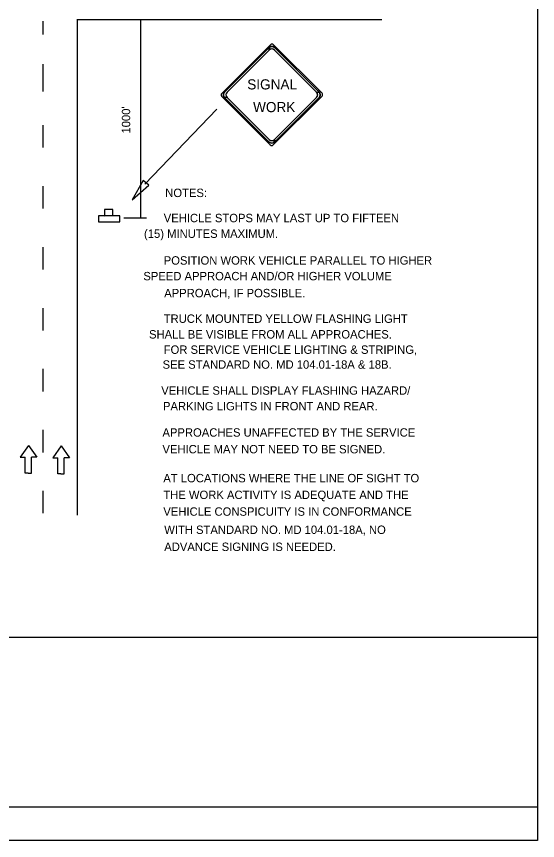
# Model space of a CAD drawing. Extents: x 1531.2 to 1538.6, y 1529.6 to 1539.9.
# Drawn here: x 1534.86 to 1538.58, y 1529.59 to 1535.48 of the extents above; entities that cross this region are included whole.
import ezdxf

# ---------------------------------------------------------------- set-up
doc = ezdxf.new("R2010")
doc.units = 0
for name, color, linetype in [('BORD-LINE', 7, 'Continuous'), ('DETL-DIMS', 7, 'Continuous'), ('DETL-LINE', 7, 'Continuous'), ('DETL-NOTE', 7, 'Continuous'), ('TTLB-TEXT', 7, 'Continuous'), ('USER-BORD', 7, 'Continuous')]:
    doc.layers.add(name, color=color, linetype=linetype)

# ---------------------------------------------------------------- blocks, each defined once
blk = doc.blocks.new('SIGN13')
at = {"layer": 'USER-BORD'}
for points in [[(-0.0134, 0.0182), (0.011, 0.0189), (0.011, 0.0371), (-0.0134, 0.0371)], [(-0.0314, 0.0182), (-0.0314, 0), (0.032, 0), (0.032, 0.0182)]]:
    blk.add_lwpolyline(points, close=True, dxfattribs=at)
blk = doc.blocks.new('DIR2')
at = {"layer": 'USER-BORD'}
for p, q in [((0, 0.0012), (-0.0342, -0.0477)), ((0, 0.0012), (0.0342, -0.0477)), ((-0.0342, -0.0477), (-0.0132, -0.0477)), ((-0.0132, -0.1133), (-0.0132, -0.0477)), ((0.0342, -0.0477), (0.0132, -0.0477)), ((0.0132, -0.1133), (0.0132, -0.0477)), ((-0.0011, -0.1133), (-0.0132, -0.1133)), ((-0.0011, -0.1133), (0.0011, -0.1133)), ((0.0011, -0.1133), (0.0132, -0.1133))]:
    blk.add_line(p, q, dxfattribs=at)

msp = doc.modelspace()

# ---------------------------------------------------------------- linework, layer by layer
at = {"layer": 'BORD-LINE'}
for p, q in [((1538.5844, 1539.9414), (1538.5844, 1531.0427)), ((1538.5844, 1531.0427), (1531.2124, 1531.0427)), ((1538.5844, 1531.0427), (1538.5844, 1529.5924)), ((1534.1128, 1529.8341), (1538.5844, 1529.8341)), ((1538.5844, 1529.5924), (1531.2124, 1529.5924))]:
    msp.add_line(p, q, dxfattribs=at)
at = {"layer": 'DETL-DIMS'}
for p, q in [((1535.7503, 1534.043), (1535.7503, 1535.4613)), ((1535.78, 1534.2836), (1536.2948, 1534.8185)), ((1535.6308, 1534.043), (1535.7909, 1534.043))]:
    msp.add_line(p, q, dxfattribs=at)
msp.add_lwpolyline([(1535.8076, 1534.2773), (1535.767, 1534.3102), (1535.6884, 1534.172)], close=True, dxfattribs=at)
at = {"layer": 'DETL-LINE'}
for p, q in [((1535.2981, 1535.092), (1535.2981, 1535.4633)), ((1535.2981, 1535.4613), (1537.4718, 1535.4613)), ((1535.054, 1535.3527), (1535.054, 1535.4485)), ((1536.6766, 1535.2801), (1536.3287, 1534.9322)), ((1536.3483, 1534.9404), (1536.6682, 1535.2603)), ((1536.6682, 1535.2419), (1536.3667, 1534.9404)), ((1537.0453, 1534.933), (1536.6982, 1535.2801)), ((1537.0065, 1534.9404), (1536.705, 1535.2419)), ((1536.7051, 1535.2603), (1537.025, 1534.9404)), ((1535.054, 1534.9801), (1535.054, 1535.1401)), ((1535.054, 1534.9463), (1535.054, 1535.1063)), ((1535.2981, 1531.9169), (1535.2981, 1535.092)), ((1536.3287, 1534.9107), (1536.6758, 1534.5636)), ((1536.6682, 1534.5836), (1536.3483, 1534.9035)), ((1536.3667, 1534.9035), (1536.6682, 1534.602)), ((1536.6974, 1534.5636), (1537.0453, 1534.9115)), ((1537.025, 1534.9035), (1536.7051, 1534.5836)), ((1536.7051, 1534.602), (1537.0065, 1534.9035)), ((1535.054, 1534.5445), (1535.054, 1534.7045)), ((1535.054, 1534.1089), (1535.054, 1534.269)), ((1535.054, 1533.6734), (1535.054, 1533.8334)), ((1535.054, 1533.2378), (1535.054, 1533.3979)), ((1535.054, 1532.8023), (1535.054, 1532.9623)), ((1535.054, 1532.3667), (1535.054, 1532.5267)), ((1535.054, 1531.9311), (1535.054, 1532.0912))]:
    msp.add_line(p, q, dxfattribs=at)
for points in [[(1536.3483, 1534.9404), (1536.659, 1535.251), (1536.6693, 1535.2614), (1536.6682, 1535.2419), (1536.3667, 1534.9404), (1536.3619, 1534.9339), (1536.3592, 1534.9243), (1536.3599, 1534.9154), (1536.3623, 1534.9093), (1536.3667, 1534.9035), (1536.3483, 1534.9035), (1536.343, 1534.911), (1536.3406, 1534.921), (1536.3414, 1534.9283), (1536.3438, 1534.9344)], [(1536.705, 1535.2603), (1537.0157, 1534.9496), (1537.026, 1534.9392), (1537.0065, 1534.9404), (1536.7051, 1535.2419), (1536.6986, 1535.2466), (1536.6889, 1535.2494), (1536.6801, 1535.2487), (1536.674, 1535.2463), (1536.6682, 1535.2419), (1536.6682, 1535.2603), (1536.6756, 1535.2655), (1536.6857, 1535.2679), (1536.693, 1535.2671), (1536.6991, 1535.2648)], [(1537.0249, 1534.9035), (1536.7142, 1534.5928), (1536.7039, 1534.5825), (1536.705, 1534.602), (1537.0065, 1534.9035), (1537.0113, 1534.91), (1537.014, 1534.9196), (1537.0133, 1534.9285), (1537.0109, 1534.9345), (1537.0065, 1534.9404), (1537.0249, 1534.9404), (1537.0302, 1534.9329), (1537.0326, 1534.9229), (1537.0318, 1534.9155), (1537.0294, 1534.9095)], [(1536.6682, 1534.5836), (1536.3575, 1534.8943), (1536.3472, 1534.9047), (1536.3667, 1534.9035), (1536.6681, 1534.602), (1536.6746, 1534.5973), (1536.6843, 1534.5945), (1536.6932, 1534.5952), (1536.6992, 1534.5976), (1536.705, 1534.602), (1536.705, 1534.5836), (1536.6976, 1534.5784), (1536.6876, 1534.576), (1536.6802, 1534.5767), (1536.6742, 1534.5791)]]:
    msp.add_lwpolyline(points, close=True, dxfattribs=at)
for centre, radius, start, end in [((1536.6874, 1535.2694), 0.0152, 45, 135), ((1536.6867, 1535.2419), 0.0261, 45, 135), ((1536.6866, 1535.2234), 0.0261, 45, 135), ((1536.3395, 1534.9215), 0.0152, 135, 225), ((1536.3667, 1534.9219), 0.0261, 135, 225), ((1536.3852, 1534.922), 0.0261, 135, 225), ((1536.9881, 1534.9219), 0.0261, 315, 45), ((1537.0066, 1534.9219), 0.0261, 315, 45), ((1537.0345, 1534.9223), 0.0152, 315, 45), ((1536.6866, 1534.6205), 0.0261, 225, 315), ((1536.6867, 1534.602), 0.0261, 225, 315), ((1536.6866, 1534.5744), 0.0152, 225, 315)]:
    msp.add_arc(centre, radius, start, end, dxfattribs=at)
at = {"layer": 'TTLB-TEXT'}
msp.add_line((1538.5844, 1529.5924), (1538.5844, 1529.5924), dxfattribs=at)

# ---------------------------------------------------------------- block references
at = {"layer": 'DETL-LINE'}
for name, p, xscale, yscale in [('SIGN13', (1535.5239, 1534.0138), 2.391312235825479, 2.391312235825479), ('DIR2', (1534.9481, 1532.4145), 1.7422373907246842, 1.742237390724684), ('DIR2', (1535.181, 1532.411), 1.7422373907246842, 1.742237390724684)]:
    msp.add_blockref(name, p, dxfattribs=dict(at, xscale=xscale, yscale=yscale))

# ---------------------------------------------------------------- texts
for s, p in [('SIGNAL', (1536.5111, 1534.9603)), ('WORK', (1536.5528, 1534.7979))]:
    msp.add_text(s, height=0.07256, dxfattribs=at).set_placement(p)
at = {"layer": 'DETL-NOTE'}
msp.add_text("1000'", height=0.06, rotation=90, dxfattribs=at).set_placement((1535.6753, 1534.6451))
for s, p in [('NOTES:', (1535.9253, 1534.1911)), ('VEHICLE STOPS MAY LAST UP TO FIFTEEN', (1535.9145, 1534.0113)), ('   (15) MINUTES MAXIMUM.', (1535.7069, 1533.8993)), ('POSITION WORK VEHICLE PARALLEL TO HIGHER', (1535.9145, 1533.7081)), ('   SPEED APPROACH AND/OR HIGHER VOLUME', (1535.7021, 1533.5961)), ('APPROACH, IF POSSIBLE.', (1535.918, 1533.4748)), ('TRUCK MOUNTED YELLOW FLASHING LIGHT', (1535.9145, 1533.2921)), ('  SHALL BE VISIBLE FROM ALL APPROACHES.', (1535.7651, 1533.1801)), ('FOR SERVICE VEHICLE LIGHTING & STRIPING,', (1535.9145, 1533.0706)), ('SEE STANDARD NO. MD 104.01-18A & 18B.', (1535.9064, 1532.9642)), ('VEHICLE SHALL DISPLAY FLASHING HAZARD/', (1535.8968, 1532.7785)), ('PARKING LIGHTS IN FRONT AND REAR.', (1535.9092, 1532.6665)), ('APPROACHES UNAFFECTED BY THE SERVICE', (1535.9054, 1532.4787)), ('VEHICLE MAY NOT NEED TO BE SIGNED.', (1535.9054, 1532.3593)), ('AT LOCATIONS WHERE THE LINE OF SIGHT TO', (1535.9117, 1532.1524)), ('THE WORK ACTIVITY IS ADEQUATE AND THE', (1535.9117, 1532.033)), ('VEHICLE CONSPICUITY IS IN CONFORMANCE', (1535.9117, 1531.9135)), ('WITH STANDARD NO. MD 104.01-18A, NO', (1535.9182, 1531.7833)), ('ADVANCE SIGNING IS NEEDED.', (1535.9182, 1531.6617))]:
    msp.add_text(s, height=0.06, dxfattribs=at).set_placement(p)

doc.saveas('drawing.dxf')
